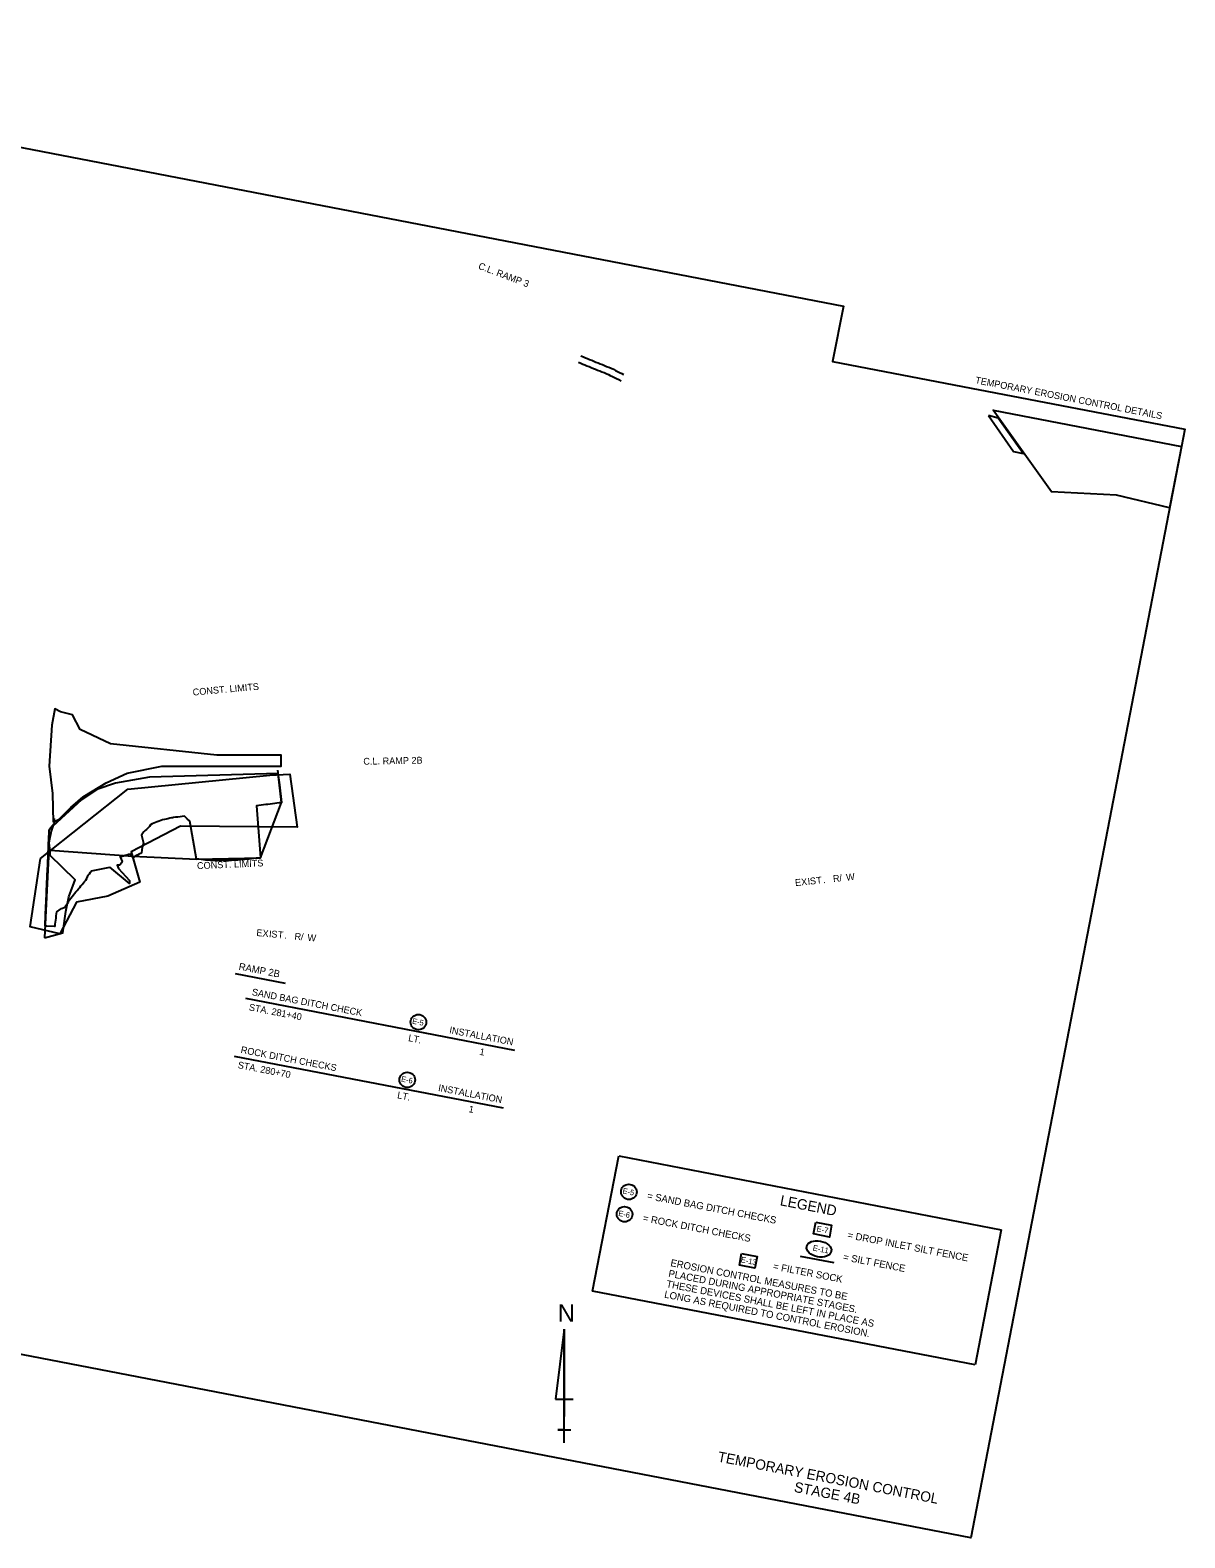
# Model space of a CAD drawing. Extents: x 607205 to 611729, y 416008 to 419873.
# Drawn here: x 610714 to 611729, y 418547 to 419873 of the extents above; entities that cross this region are included whole.
import ezdxf

# ---------------------------------------------------------------- set-up
doc = ezdxf.new("R2010")
doc.units = 0
for name, color, linetype in [('Default', 7, 'Continuous'), ('G-ANNO-TEXT', 7, 'Continuous'), ('Level 1', 7, 'Continuous'), ('Level 44', 7, 'Continuous'), ('R_Concrete', 7, 'Continuous'), ('R_Draft', 7, 'Continuous'), ('R_Perimeter', 7, 'Continuous'), ('TP_Mask', 7, 'Continuous'), ('X_ARROWS_LEGEND', 7, 'Continuous')]:
    doc.layers.add(name, color=color, linetype=linetype)

msp = doc.modelspace()

# ---------------------------------------------------------------- linework, layer by layer
at = {"layer": 'G-ANNO-TEXT'}
for p, q in [((610894.1, 419043.7), (610937.9, 419035.2)), ((610902.9, 419022.1), (611139.5, 418976.4)), ((610893, 418971.2), (611129.7, 418925.5))]:
    msp.add_line(p, q, dxfattribs=at)
at = {"layer": 'Level 44'}
msp.add_lwpolyline([(611390.6, 418795.3), (611420.2, 418789.6)], dxfattribs=at)
at = {"layer": 'R_Concrete'}
for points in [[(611195.8, 419581.3), (611197.8, 419580.5), (611199.6, 419579.7), (611201.5, 419578.9), (611203.3, 419578.2), (611205.2, 419577.4), (611207.1, 419576.6), (611208.9, 419575.9), (611210.8, 419575.1), (611212.6, 419574.4), (611214.5, 419573.6), (611216.4, 419572.8), (611218.3, 419572.1), (611220.3, 419571.3), (611222.1, 419570.6), (611223.8, 419569.7), (611225.6, 419568.8), (611227.5, 419567.9), (611229.3, 419566.9), (611231.2, 419566), (611233.3, 419565)], [(611197.8, 419586.9), (611200.1, 419586), (611201.9, 419585.2), (611203.8, 419584.5), (611205.6, 419583.7), (611207.5, 419583), (611209.3, 419582.2), (611211.2, 419581.4), (611213, 419580.7), (611214.9, 419579.9), (611216.8, 419579.2), (611218.7, 419578.4), (611220.6, 419577.6), (611222.5, 419576.9), (611224.5, 419576.1), (611226.5, 419575.1), (611228.3, 419574.1), (611230.2, 419573.2), (611232, 419572.3), (611233.9, 419571.4), (611235.4, 419570.6), (611235.5, 419570.6)]]:
    msp.add_lwpolyline(points, dxfattribs=at)
at = {"layer": 'R_Perimeter'}
for points in [[(610931.3, 419222.7), (610932.1, 419215.7), (610932.9, 419209.7), (610934.8, 419194.2), (610934.8, 419193.9), (610934.7, 419193.9), (610932.7, 419193.7), (610930.7, 419193.4), (610928.7, 419193.2), (610926.7, 419193), (610924.8, 419192.7), (610922.8, 419192.5), (610920.8, 419192.3), (610918.8, 419192), (610916.8, 419191.8), (610914.8, 419191.6), (610912.8, 419191.3), (610916.3, 419145.6), (610914.3, 419145.3), (610912.3, 419145.1), (610910.4, 419144.8), (610908.4, 419144.6), (610906.4, 419144.4), (610904.4, 419144.2), (610902.4, 419144), (610900.4, 419143.9), (610898.4, 419143.7), (610896.4, 419143.5), (610894.4, 419143.4), (610892.4, 419143.3), (610891.3, 419143.3), (610890.4, 419143.2), (610888.4, 419143.2), (610886.4, 419143.2), (610884.4, 419143.2), (610882.4, 419143.1), (610880.4, 419143), (610878.4, 419142.9), (610876.4, 419142.8), (610874.3, 419143), (610872.3, 419143.2), (610870.3, 419143.4), (610868.2, 419143.5), (610866.2, 419143.8), (610864.1, 419144), (610862.1, 419144.2), (610860.1, 419144.4), (610854, 419177.7), (610851.8, 419179.9), (610849.5, 419182), (610847.5, 419181.8), (610845.5, 419181.6), (610843.5, 419181.3), (610841.6, 419181.1), (610839.6, 419180.8), (610838.8, 419180.7), (610838, 419180.5), (610836.4, 419180.3), (610834.8, 419179.9), (610833.2, 419179.6), (610831.7, 419179.2), (610830.1, 419178.8), (610828.5, 419178.3), (610827, 419177.8), (610825.5, 419177.2), (610824, 419176.6), (610822.5, 419176), (610821, 419175.4), (610819.6, 419174.6), (610818.5, 419173), (610817.3, 419171.5), (610816.1, 419170.5), (610814.8, 419169.4), (610813.7, 419168.2), (610812.6, 419166.9), (610812, 419166.3), (610811.6, 419165.4), (610813.4, 419158.3), (610812.7, 419156.6), (610812.2, 419154.7), (610812, 419152.1), (610811.7, 419150), (610810.6, 419149.4), (610809.4, 419148.8), (610808.3, 419148.2), (610807.2, 419147.5), (610806.1, 419146.8), (610805.1, 419146.1), (610804, 419145.4), (610801.5, 419148.7), (610800.1, 419148.3), (610798.7, 419147.9), (610797.3, 419147.5), (610795.9, 419147), (610794.5, 419146.5), (610792.8, 419146.3), (610794.5, 419142.3), (610793.9, 419141), (610793, 419140), (610792, 419139.1), (610790.2, 419139), (610791.4, 419136), (610801, 419125.6), (610801, 419124.2), (610801, 419122.8), (610783.9, 419137.2)], [(610931.3, 419222.7), (610932.1, 419215.7), (610932.9, 419209.7), (610934.8, 419194.2), (610934.8, 419193.9), (610934.7, 419193.9), (610932.7, 419193.7), (610930.7, 419193.4), (610928.7, 419193.2), (610926.7, 419193), (610924.8, 419192.7), (610922.8, 419192.5), (610920.8, 419192.3), (610918.8, 419192), (610916.8, 419191.8), (610914.8, 419191.6), (610912.8, 419191.3), (610916.3, 419145.6), (610914.3, 419145.3), (610912.3, 419145.1), (610910.4, 419144.8), (610908.4, 419144.6), (610906.4, 419144.4), (610904.4, 419144.2), (610902.4, 419144), (610900.4, 419143.9), (610898.4, 419143.7), (610896.4, 419143.5), (610894.4, 419143.4), (610892.4, 419143.3), (610891.3, 419143.3), (610890.4, 419143.2), (610888.4, 419143.2), (610886.4, 419143.2), (610884.4, 419143.2), (610882.4, 419143.1), (610880.4, 419143), (610878.4, 419142.9), (610876.4, 419142.8), (610874.3, 419143), (610872.3, 419143.2), (610870.3, 419143.4), (610868.2, 419143.5), (610866.2, 419143.8), (610864.1, 419144), (610862.1, 419144.2), (610860.1, 419144.4), (610854, 419177.7), (610851.8, 419179.9), (610849.5, 419182), (610847.5, 419181.8), (610845.5, 419181.6), (610843.5, 419181.3), (610841.6, 419181.1), (610839.6, 419180.8), (610838.8, 419180.7), (610838, 419180.5), (610836.4, 419180.3), (610834.8, 419179.9), (610833.2, 419179.6), (610831.7, 419179.2), (610830.1, 419178.8), (610828.5, 419178.3), (610827, 419177.8), (610825.5, 419177.2), (610824, 419176.6), (610822.5, 419176), (610821, 419175.4), (610819.6, 419174.6), (610818.5, 419173), (610817.3, 419171.5), (610816.1, 419170.5), (610814.8, 419169.4), (610813.7, 419168.2), (610812.6, 419166.9), (610812, 419166.3), (610811.6, 419165.4), (610813.4, 419158.3), (610812.7, 419156.6), (610812.2, 419154.7), (610812, 419152.1), (610811.7, 419150), (610810.6, 419149.4), (610809.4, 419148.8), (610808.3, 419148.2), (610807.2, 419147.5), (610806.1, 419146.8), (610805.1, 419146.1), (610804, 419145.4), (610801.5, 419148.7), (610800.1, 419148.3), (610798.7, 419147.9), (610797.3, 419147.5), (610795.9, 419147), (610794.5, 419146.5), (610792.8, 419146.3), (610794.5, 419142.3), (610793.9, 419141), (610793, 419140), (610792, 419139.1), (610790.2, 419139), (610791.4, 419136), (610801, 419125.6), (610801, 419124.2), (610801, 419122.8), (610783.9, 419137.2)], [(610735.6, 419085.2), (610735.2, 419085.2), (610728.3, 419085.5), (610727.9, 419085.5), (610727.8, 419085.5), (610726.8, 419085.5), (610726.9, 419087.5), (610727, 419089.5), (610727.1, 419091.5), (610727.1, 419093.5), (610727.2, 419095.5), (610727.3, 419097.6), (610727.4, 419099.6), (610727.5, 419101.6), (610727.6, 419103.6), (610727.7, 419105.7), (610727.8, 419107.7), (610727.9, 419109.8), (610728, 419111.9), (610728.1, 419114), (610728.1, 419116.1), (610728.2, 419118.2), (610728.3, 419120.4), (610728.4, 419122.5), (610728.5, 419124.7), (610728.6, 419126.9), (610728.7, 419129.1), (610728.8, 419131.4), (610728.9, 419133.7), (610729, 419136), (610729.1, 419138.3), (610729.2, 419140.7), (610729.3, 419143.1), (610729.4, 419145.6), (610729.5, 419148), (610729.6, 419150.6), (610729.7, 419153.1), (610729.8, 419155.7), (610729.9, 419158.4), (610730, 419161.1), (610730.1, 419163.9), (610730.3, 419166.7), (610730.4, 419170.1), (610731.6, 419171.7), (610733.1, 419173.6), (610734.6, 419175.5), (610735.1, 419176.1), (610735.1, 419180)], [(610735.6, 419085.2), (610735.2, 419085.2), (610728.3, 419085.5), (610727.9, 419085.5), (610727.8, 419085.5), (610726.8, 419085.5), (610726.9, 419087.5), (610727, 419089.5), (610727.1, 419091.5), (610727.1, 419093.5), (610727.2, 419095.5), (610727.3, 419097.6), (610727.4, 419099.6), (610727.5, 419101.6), (610727.6, 419103.6), (610727.7, 419105.7), (610727.8, 419107.7), (610727.9, 419109.8), (610728, 419111.9), (610728.1, 419114), (610728.1, 419116.1), (610728.2, 419118.2), (610728.3, 419120.4), (610728.4, 419122.5), (610728.5, 419124.7), (610728.6, 419126.9), (610728.7, 419129.1), (610728.8, 419131.4), (610728.9, 419133.7), (610729, 419136), (610729.1, 419138.3), (610729.2, 419140.7), (610729.3, 419143.1), (610729.4, 419145.6), (610729.5, 419148), (610729.6, 419150.6), (610729.7, 419153.1), (610729.8, 419155.7), (610729.9, 419158.4), (610730, 419161.1), (610730.1, 419163.9), (610730.3, 419166.7), (610730.4, 419170.1)], [(610735.6, 419085.2), (610735.7, 419087), (610735.9, 419088.9), (610736.2, 419090.7), (610736.5, 419092.5), (610736.7, 419094.4), (610737, 419096.2), (610737.3, 419098), (610740.5, 419100.3), (610740.5, 419100.3), (610741.4, 419101), (610744.4, 419102.2), (610745.5, 419103.8), (610746.4, 419105.4), (610747.4, 419106.9), (610748.4, 419108.4), (610749.4, 419109.9), (610750.5, 419111.4), (610751.7, 419112.8), (610752.8, 419114.1), (610754, 419115.5), (610755.1, 419116.8), (610756.3, 419118.2), (610757.4, 419119.5), (610758.4, 419120.8), (610759.5, 419122.1), (610760.5, 419123.4), (610761.6, 419124.7), (610762.7, 419125.9), (610763.4, 419127.4), (610764, 419128.9), (610764.8, 419130.2), (610765.8, 419131.5), (610766.8, 419132.8), (610767.7, 419134.1), (610783.9, 419137.2)]]:
    msp.add_lwpolyline(points, dxfattribs=at)
at = {"layer": 'TP_Mask'}
for points in [[(610171.9, 419873.3), (611428.7, 419630.7), (611419.3, 419582), (611533.5, 419560), (611729, 419522.3), (611726, 419507.1), (611540.8, 418547.5), (609974.4, 418849.9)], [(611726, 419507.1), (611715.6, 419453.2), (611668.9, 419464.5), (611611.7, 419467.4), (611560.4, 419539)], [(611556.3, 419534.4), (611578.4, 419502.9), (611586.7, 419501), (611564.9, 419532.1)], [(610733.8, 419176.9), (610739.3, 419179.5), (610749.4, 419189.8), (610760.3, 419199.1), (610780.4, 419211.4), (610799.1, 419220), (610829.5, 419226.1), (610899.4, 419226.2), (610934.4, 419226.2), (610934.4, 419235.8), (610877.7, 419235.8), (610784.2, 419245.8), (610757.7, 419258.4), (610750.8, 419271.2), (610740.5, 419273.9), (610735.5, 419276.6), (610732.8, 419262), (610730.3, 419226), (610733.3, 419202.1)], [(610722.9, 419144.8), (610799.7, 419205.8), (610924.3, 419218.3), (610942, 419219), (610948.4, 419172.3), (610846, 419173.2), (610802.6, 419150.7), (610810.1, 419124), (610782, 419111.7), (610754.4, 419106.6), (610739.9, 419078.7), (610713.7, 419084.9)], [(610726.4, 419075.1), (610742.4, 419079.4), (610745, 419098.4), (610747.8, 419111.3), (610753.2, 419126), (610731, 419147.8), (610731.2, 419152.3), (610804, 419146.9), (610860.1, 419144.4), (610916.3, 419145.6), (610934.8, 419194.2), (610931.7, 419219.6), (610818.7, 419216.5), (610788.6, 419211), (610772.4, 419205.6), (610758.7, 419196.5), (610733.7, 419173.4), (610732.3, 419169), (610730.3, 419160.3), (610730, 419158.5), (610731, 419151.5), (610731, 419151.2), (610730.9, 419147.8), (610729.9, 419146.6)]]:
    msp.add_lwpolyline(points, close=True, dxfattribs=at)
at = {"layer": 'X_ARROWS_LEGEND'}
for p, q in [((611208.2, 418764.5), (611231.2, 418883.3)), ((611231.2, 418883.3), (611567.6, 418818.4)), ((611567.6, 418818.4), (611544.7, 418699.5)), ((611544.7, 418699.5), (611208.2, 418764.5)), ((611183.3, 418731), (611175.6, 418669.5)), ((611183.3, 418631), (611183.3, 418731)), ((611183.3, 418731), (611183.3, 418654.1)), ((611175.6, 418669.5), (611191, 418669.5)), ((611183.3, 418631), (611183.3, 418654.1)), ((611183.3, 418642.6), (611177.6, 418642.6)), ((611177.6, 418642.6), (611189.1, 418642.6)), ((611183.3, 418631), (611183.3, 418642.6))]:
    msp.add_line(p, q, dxfattribs=at)
for points in [[(611404.6, 418825), (611418.3, 418822.4), (611416.4, 418812), (611402.6, 418814.7)], [(611339.2, 418797.6), (611353, 418794.9), (611351, 418784.6), (611337.3, 418787.2)]]:
    msp.add_lwpolyline(points, close=True, dxfattribs=at)
for centre, major_axis, ratio in [((611055.1, 419001), (-6.76, 1.31), 0.97521), ((611045.3, 418950.2), (-6.76, 1.31), 0.97521), ((611240.1, 418851.7), (-6.76, 1.31), 0.97521), ((611236.3, 418832.1), (-6.76, 1.31), 0.97521), ((611407.3, 418801.6), (10.8, -2.1), 0.638788)]:
    msp.add_ellipse(centre, major_axis=major_axis, ratio=ratio, dxfattribs=at)

# ---------------------------------------------------------------- texts
at = {"layer": 'Default'}
for s, rotation, p in [('C.L. RAMP 3', 339.2097, (611107.2, 419663.6)), ('C.L. RAMP 2B', 1.1692, (611006.7, 419227.3))]:
    msp.add_text(s, height=6, rotation=rotation, dxfattribs=at).set_placement(p)
at = {"layer": 'G-ANNO-TEXT'}
for s, height, p in [('TEMPORARY EROSION CONTROL DETAILS', 6, (611544.3, 419562.8)), ('RAMP 2B', 6.25, (610896.7, 419047.1)), ('SAND BAG DITCH CHECK', 6, (610908.3, 419024.8)), ('STA. 281+40', 6, (610905.7, 419011.4)), ('INSTALLATION ', 6, (611081.9, 418991.3)), ('ROCK DITCH CHECKS', 6, (610898.5, 418974)), ('LT. ', 6, (611045.8, 418984.4)), ('STA. 280+70', 6, (610895.9, 418960.6)), ('1', 6, (611108.4, 418972.3)), ('LT. ', 6, (611036.1, 418934.1)), ('INSTALLATION ', 6, (611072.1, 418940.5)), ('1', 6, (611098.9, 418921.9)), ('TEMPORARY EROSION CONTROL ', 9, (611317.7, 418614.7)), ('STAGE 4B', 9, (611384.9, 418588))]:
    msp.add_text(s, height=height, rotation=349.0745, dxfattribs=at).set_placement(p)
at = {"layer": 'Level 1'}
for s, p in [('= DROP INLET SILT FENCE', (611431.9, 418811)), ('= SILT FENCE', (611428.1, 418791.7)), ('= FILTER SOCK', (611366.5, 418783.5))]:
    msp.add_text(s, height=6.25, rotation=349.0745, dxfattribs=at).set_placement(p)
at = {"layer": 'R_Draft'}
for s, rotation, p in [('CONST. LIMITS', 5.1083, (610856.9, 419288.1)), ('CONST. LIMITS', 2.4647, (610860.5, 419135.5)), ('E', 5.9666, (611386.5, 419120.6)), ('X', 5.9666, (611391.9, 419121.1)), ('I', 5.9666, (611397.6, 419121.7)), ('S', 5.9666, (611399.6, 419121.9)), ('T', 5.9666, (611405.2, 419122.5)), ('R', 5.9666, (611419.9, 419124.1)), ('/', 5.9666, (611425.5, 419124.7)), ('W', 5.9666, (611431.4, 419125.3)), ('.', 5.9666, (611411, 419123.1)), ('E', 354.5081, (610912.4, 419076.8)), ('X', 354.5081, (610917.8, 419076.3)), ('I', 354.5081, (610923.5, 419075.7)), ('S', 354.5081, (610925.5, 419075.6)), ('T', 354.5081, (610931.2, 419075)), ('.', 354.5081, (610937, 419074.5)), ('R', 354.5081, (610945.9, 419073.6)), ('/', 354.5081, (610951.5, 419073.1)), ('W', 354.5081, (610957.3, 419072.5))]:
    msp.add_text(s, height=6, rotation=rotation, dxfattribs=at).set_placement(p)
at = {"layer": 'X_ARROWS_LEGEND'}
for s, height, rotation, p in [('E-5', 4.88, 349.0745, (611049.3, 418999.7)), ('E-6', 4.88, 349.0745, (611039.6, 418948.8)), ('E-5', 4.88, 349.0745, (611234.3, 418850.4)), ('= SAND BAG DITCH CHECKS', 6.25, 349.0745, (611255.8, 418845.5)), ('LEGEND', 9.14, 349.0745, (611372.5, 418840)), ('E-6', 4.88, 349.0745, (611230.6, 418830.7)), ('= ROCK DITCH CHECKS', 6.25, 349.0745, (611252, 418825.9)), ('E-7', 5, 348.6922, (611404.8, 418817.1)), ('E-13', 5, 348.6922, (611338.2, 418789.9)), ('E-11', 5, 349.0745, (611401.5, 418800.2)), ('PLACED DURING APPROPRIATE STAGES. ', 6.25, 349.0745, (611274.5, 418777.2)), ('EROSION CONTROL MEASURES TO BE', 6.25, 349.0745, (611276.3, 418786.5)), ('THESE DEVICES SHALL BE LEFT IN PLACE AS ', 6.25, 349.0745, (611272.7, 418768)), ('LONG AS REQUIRED TO CONTROL EROSION.', 6.25, 349.0745, (611270.9, 418758.8)), ('N', 15.4, 360, (611177.7, 418737.5))]:
    msp.add_text(s, height=height, rotation=rotation, dxfattribs=at).set_placement(p)

doc.saveas('drawing.dxf')
